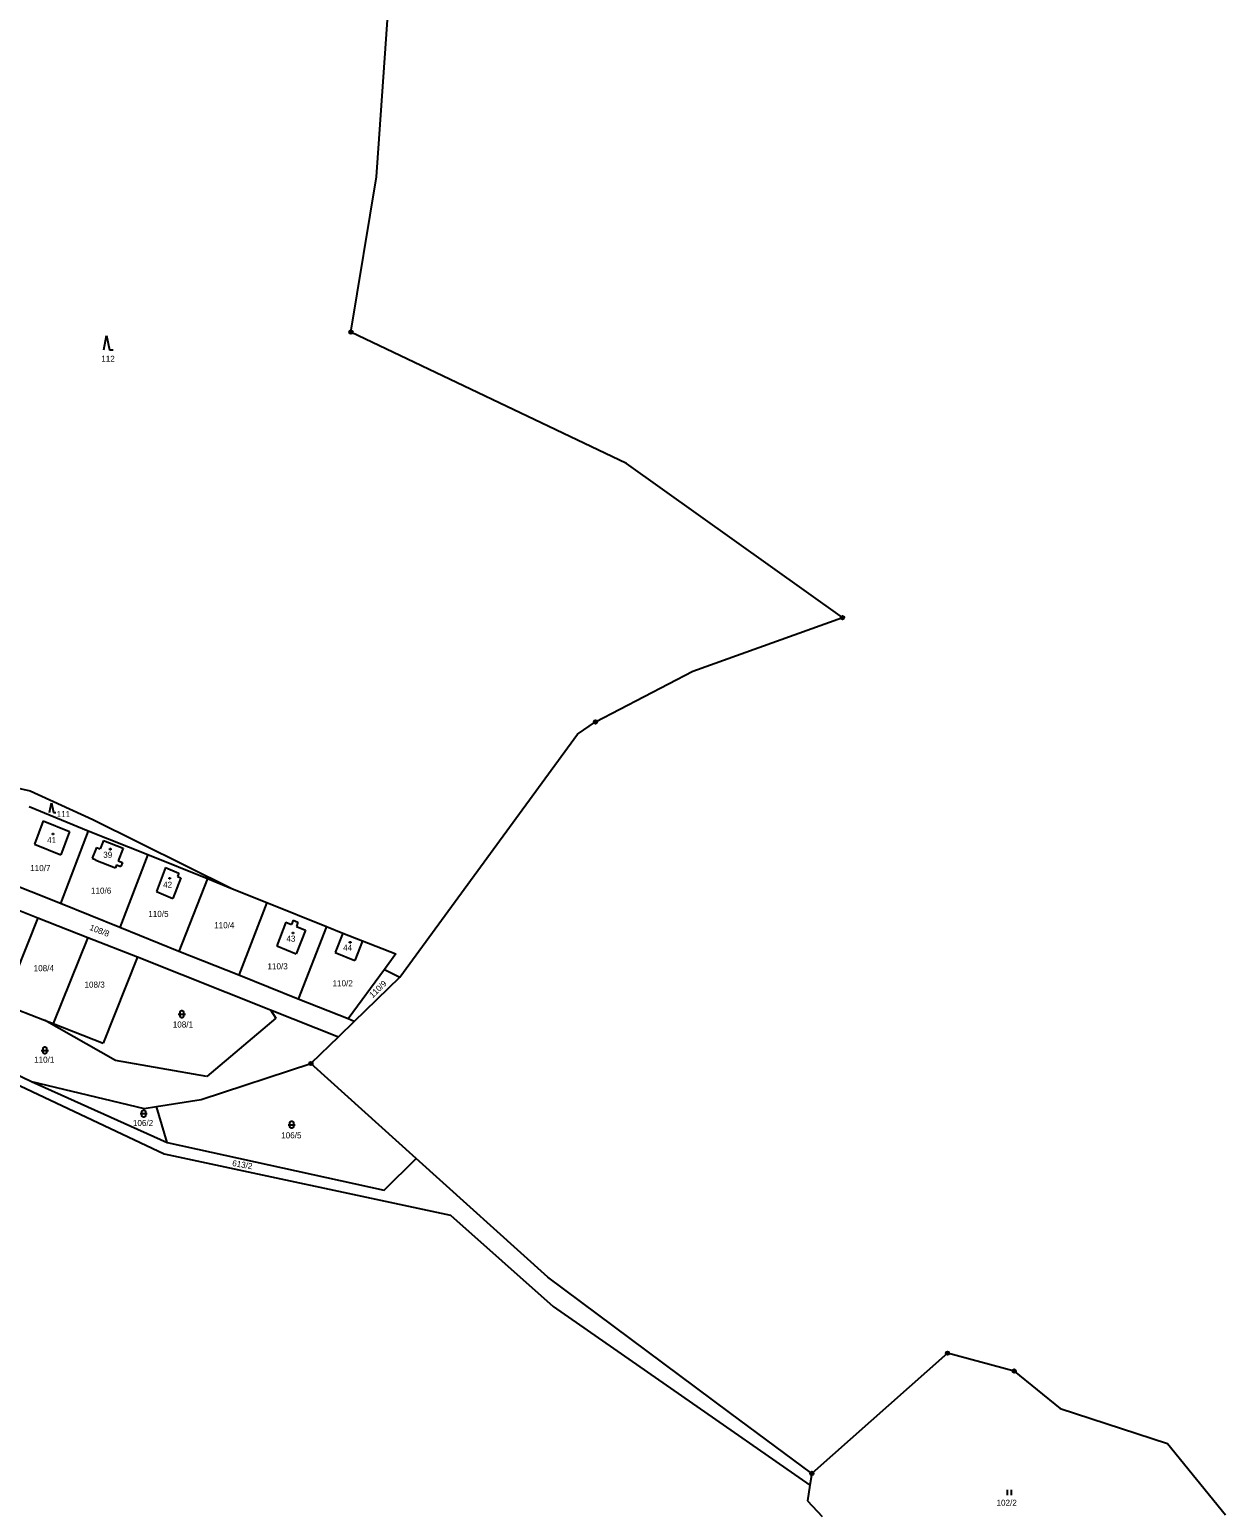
# Model space of a CAD drawing. Extents: x -794421 to -792735, y -1117671 to -1115559.
# Drawn here: x -793109.5 to -792774.2, y -1116832.2 to -1116417 of the extents above; entities that cross this region are included whole.
import ezdxf

# ---------------------------------------------------------------- set-up
doc = ezdxf.new("R2010")
doc.units = 0
for name, color, linetype in [('Vrstva 1', 7, 'Continuous'), ('Vrstva 14', 7, 'Continuous'), ('Vrstva 15', 7, 'Continuous'), ('Vrstva 23', 7, 'Continuous'), ('Vrstva 25', 7, 'Continuous'), ('Vrstva 28', 7, 'Continuous'), ('Vrstva 3', 7, 'Continuous'), ('Vrstva 4', 7, 'Continuous')]:
    doc.layers.add(name, color=color, linetype=linetype)

msp = doc.modelspace()

# ---------------------------------------------------------------- linework, layer by layer
at = {"layer": 'Vrstva 1'}
for p, q in [((-793154.11, -1116620.49), (-793109.33, -1116630.44)), ((-793109.33, -1116630.44), (-793091.78, -1116638.52)), ((-793109.67, -1116634.81), (-793093.04, -1116641.68)), ((-793105.7, -1116638.82), (-793108.16, -1116645.35)), ((-793105.7, -1116638.82), (-793098.28, -1116641.83)), ((-793091.78, -1116638.52), (-793052.59, -1116657.89)), ((-793093.04, -1116641.68), (-793100.84, -1116662.06)), ((-793098.28, -1116641.83), (-793100.74, -1116648.36)), ((-793093.04, -1116641.68), (-793076.37, -1116648.32)), ((-793088.79, -1116644.35), (-793089.72, -1116646.72)), ((-793088.79, -1116644.35), (-793083.29, -1116646.5)), ((-793108.16, -1116645.35), (-793100.74, -1116648.36)), ((-793090.74, -1116646.32), (-793091.92, -1116649.35)), ((-793090.74, -1116646.32), (-793089.72, -1116646.72)), ((-793083.29, -1116646.5), (-793084.66, -1116650.02)), ((-793076.37, -1116648.32), (-793084.21, -1116668.75)), ((-793076.37, -1116648.32), (-793059.64, -1116655.06)), ((-793091.92, -1116649.35), (-793090.9, -1116649.75)), ((-793090.9, -1116649.75), (-793090.95, -1116649.87)), ((-793090.95, -1116649.87), (-793085.44, -1116652.01)), ((-793085.11, -1116651.16), (-793085.44, -1116652.01)), ((-793085.11, -1116651.16), (-793083.92, -1116651.62)), ((-793084.66, -1116650.02), (-793083.47, -1116650.49)), ((-793083.47, -1116650.49), (-793083.92, -1116651.62)), ((-793071.36, -1116651.92), (-793073.93, -1116658.64)), ((-793071.36, -1116651.92), (-793067.63, -1116653.49)), ((-793100.84, -1116662.06), (-793117.32, -1116655.46)), ((-793067.13, -1116654.87), (-793069.32, -1116660.58)), ((-793067.63, -1116653.49), (-793068.02, -1116654.5)), ((-793068.02, -1116654.5), (-793067.13, -1116654.87)), ((-793059.64, -1116655.06), (-793067.62, -1116675.49)), ((-793059.64, -1116655.06), (-793052.59, -1116657.89)), ((-793121.12, -1116660.55), (-793107.16, -1116666.03)), ((-793073.93, -1116658.64), (-793069.32, -1116660.58)), ((-793052.59, -1116657.89), (-793042.94, -1116661.77)), ((-793084.21, -1116668.75), (-793100.84, -1116662.06)), ((-793042.94, -1116661.77), (-793050.85, -1116682.09)), ((-793042.94, -1116661.77), (-793026.25, -1116668.51)), ((-793107.16, -1116666.03), (-793116.82, -1116690.23)), ((-793107.16, -1116666.03), (-793093.19, -1116671.52)), ((-793067.62, -1116675.49), (-793084.21, -1116668.75)), ((-793037.65, -1116667.23), (-793040.16, -1116673.85)), ((-793037.65, -1116667.23), (-793036.03, -1116667.9)), ((-793035.58, -1116666.7), (-793036.03, -1116667.9)), ((-793035.58, -1116666.7), (-793034.24, -1116667.25)), ((-793032.15, -1116669.5), (-793034.72, -1116676.1)), ((-793034.24, -1116667.25), (-793034.7, -1116668.45)), ((-793034.7, -1116668.45), (-793032.15, -1116669.5)), ((-793026.25, -1116668.51), (-793034.18, -1116688.82)), ((-793026.25, -1116668.51), (-793021.71, -1116670.3)), ((-793093.19, -1116671.52), (-793102.85, -1116695.69)), ((-793093.19, -1116671.52), (-793079.23, -1116677)), ((-793021.71, -1116670.3), (-793023.77, -1116675.81)), ((-793021.71, -1116670.3), (-793016.19, -1116672.48)), ((-793016.19, -1116672.48), (-793018.26, -1116677.98)), ((-793016.19, -1116672.48), (-793006.82, -1116676.17)), ((-793079.23, -1116677), (-793088.88, -1116701.16)), ((-793079.23, -1116677), (-793041.96, -1116691.82)), ((-793050.85, -1116682.09), (-793067.62, -1116675.49)), ((-793040.16, -1116673.85), (-793034.72, -1116676.1)), ((-793023.77, -1116675.81), (-793018.26, -1116677.98)), ((-793006.82, -1116676.17), (-793010, -1116680.5)), ((-793010, -1116680.5), (-793020.21, -1116694.41)), ((-793010, -1116680.5), (-793005.71, -1116682.65)), ((-793175.39, -1116683.36), (-793071.81, -1116732.17)), ((-793034.18, -1116688.82), (-793050.85, -1116682.09)), ((-793161.81, -1116686.74), (-793108.95, -1116711.9)), ((-793116.82, -1116690.23), (-793105.32, -1116694.73)), ((-793020.21, -1116694.41), (-793034.18, -1116688.82)), ((-793040.49, -1116694.16), (-793059.84, -1116710.53)), ((-793041.96, -1116691.82), (-793040.49, -1116694.16)), ((-793041.96, -1116691.82), (-793022.91, -1116699.39)), ((-793018.5, -1116695.1), (-793020.21, -1116694.41)), ((-793105.32, -1116694.73), (-793102.85, -1116695.69)), ((-793085.37, -1116706.02), (-793105.32, -1116694.73)), ((-793102.85, -1116695.69), (-793088.88, -1116701.16)), ((-793059.84, -1116710.53), (-793085.37, -1116706.02)), ((-793061.38, -1116716.94), (-793030.61, -1116706.88)), ((-793108.95, -1116711.9), (-793077.4, -1116719.53)), ((-793108.95, -1116711.9), (-793070.89, -1116729.03)), ((-793077.4, -1116719.53), (-793073.91, -1116718.97)), ((-793073.91, -1116718.97), (-793061.38, -1116716.94)), ((-793070.89, -1116729.03), (-793073.91, -1116718.97)), ((-793070.89, -1116729.03), (-793010.09, -1116742.37)), ((-793071.81, -1116732.17), (-792991.43, -1116749.42)), ((-793010.09, -1116742.37), (-793001.09, -1116733.51)), ((-792991.43, -1116749.42), (-792962.66, -1116774.99)), ((-792962.66, -1116774.99), (-792890.67, -1116825.12)), ((-792890.14, -1116821.82), (-792890.67, -1116825.12)), ((-792890.67, -1116825.12), (-792891.38, -1116829.52)), ((-792891.38, -1116829.52), (-792887.25, -1116833.92))]:
    msp.add_line(p, q, dxfattribs=at)
at = {"layer": 'Vrstva 23'}
for p, q in [((-793088.7, -1116506.81), (-793087.9, -1116502.81)), ((-793087.9, -1116502.81), (-793087.1, -1116506.81)), ((-793087.1, -1116506.81), (-793086.1, -1116506.81)), ((-793103.896, -1116636.49), (-793103.36, -1116633.81)), ((-793103.36, -1116633.81), (-793102.824, -1116636.49)), ((-793102.824, -1116636.49), (-793102.154, -1116636.49)), ((-793067.82, -1116693.05), (-793065.82, -1116693.05)), ((-793067.32, -1116692.45), (-793067.22, -1116692.25)), ((-793067.32, -1116693.65), (-793067.32, -1116692.45)), ((-793067.22, -1116693.85), (-793067.32, -1116693.65)), ((-793067.22, -1116692.25), (-793067.12, -1116692.15)), ((-793067.12, -1116693.95), (-793067.22, -1116693.85)), ((-793067.12, -1116692.15), (-793066.92, -1116692.05)), ((-793066.92, -1116694.05), (-793067.12, -1116693.95)), ((-793066.92, -1116692.05), (-793066.72, -1116692.05)), ((-793066.72, -1116694.05), (-793066.92, -1116694.05)), ((-793066.72, -1116692.05), (-793066.52, -1116692.15)), ((-793066.52, -1116693.95), (-793066.72, -1116694.05)), ((-793066.52, -1116692.15), (-793066.42, -1116692.25)), ((-793066.42, -1116693.85), (-793066.52, -1116693.95)), ((-793066.42, -1116692.25), (-793066.32, -1116692.45)), ((-793066.32, -1116693.65), (-793066.42, -1116693.85)), ((-793066.32, -1116692.45), (-793066.32, -1116693.65)), ((-793105.73, -1116702.61), (-793105.63, -1116702.41)), ((-793105.73, -1116703.81), (-793105.73, -1116702.61)), ((-793105.63, -1116702.41), (-793105.53, -1116702.31)), ((-793105.53, -1116702.31), (-793105.33, -1116702.21)), ((-793105.33, -1116702.21), (-793105.13, -1116702.21)), ((-793105.13, -1116702.21), (-793104.93, -1116702.31)), ((-793104.93, -1116702.31), (-793104.83, -1116702.41)), ((-793104.83, -1116702.41), (-793104.73, -1116702.61)), ((-793104.73, -1116702.61), (-793104.73, -1116703.81)), ((-793106.23, -1116703.21), (-793104.23, -1116703.21)), ((-793105.63, -1116704.01), (-793105.73, -1116703.81)), ((-793105.53, -1116704.11), (-793105.63, -1116704.01)), ((-793105.33, -1116704.21), (-793105.53, -1116704.11)), ((-793105.13, -1116704.21), (-793105.33, -1116704.21)), ((-793104.93, -1116704.11), (-793105.13, -1116704.21)), ((-793104.83, -1116704.01), (-793104.93, -1116704.11)), ((-793104.73, -1116703.81), (-793104.83, -1116704.01)), ((-793078.5, -1116720.93), (-793076.5, -1116720.93)), ((-793078, -1116720.33), (-793077.9, -1116720.13)), ((-793078, -1116721.53), (-793078, -1116720.33)), ((-793077.9, -1116721.73), (-793078, -1116721.53)), ((-793077.9, -1116720.13), (-793077.8, -1116720.03)), ((-793077.8, -1116721.83), (-793077.9, -1116721.73)), ((-793077.8, -1116720.03), (-793077.6, -1116719.93)), ((-793077.6, -1116721.93), (-793077.8, -1116721.83)), ((-793077.6, -1116719.93), (-793077.4, -1116719.93)), ((-793077.4, -1116721.93), (-793077.6, -1116721.93)), ((-793077.4, -1116719.93), (-793077.2, -1116720.03)), ((-793077.2, -1116721.83), (-793077.4, -1116721.93)), ((-793077.2, -1116720.03), (-793077.1, -1116720.13)), ((-793077.1, -1116721.73), (-793077.2, -1116721.83)), ((-793077.1, -1116720.13), (-793077, -1116720.33)), ((-793077, -1116721.53), (-793077.1, -1116721.73)), ((-793077, -1116720.33), (-793077, -1116721.53)), ((-793036.52, -1116723.44), (-793036.42, -1116723.24)), ((-793036.52, -1116724.64), (-793036.52, -1116723.44)), ((-793036.42, -1116723.24), (-793036.32, -1116723.14)), ((-793036.32, -1116723.14), (-793036.12, -1116723.04)), ((-793036.12, -1116723.04), (-793035.92, -1116723.04)), ((-793035.92, -1116723.04), (-793035.72, -1116723.14)), ((-793035.72, -1116723.14), (-793035.62, -1116723.24)), ((-793035.62, -1116723.24), (-793035.52, -1116723.44)), ((-793035.52, -1116723.44), (-793035.52, -1116724.64)), ((-793037.02, -1116724.04), (-793035.02, -1116724.04)), ((-793036.42, -1116724.84), (-793036.52, -1116724.64)), ((-793036.32, -1116724.94), (-793036.42, -1116724.84)), ((-793036.12, -1116725.04), (-793036.32, -1116724.94)), ((-793035.92, -1116725.04), (-793036.12, -1116725.04)), ((-793035.72, -1116724.94), (-793035.92, -1116725.04)), ((-793035.62, -1116724.84), (-793035.72, -1116724.94)), ((-793035.52, -1116724.64), (-793035.62, -1116724.84)), ((-792835.29, -1116827.94), (-792835.29, -1116826.44)), ((-792834.29, -1116826.44), (-792834.29, -1116827.94))]:
    msp.add_line(p, q, dxfattribs=at)
at = {"layer": 'Vrstva 25'}
for p, q in [((-793103.06, -1116642.38), (-793102.76, -1116642.38)), ((-793103.06, -1116642.68), (-793103.06, -1116642.38)), ((-793102.76, -1116642.68), (-793103.06, -1116642.68)), ((-793102.76, -1116642.38), (-793102.76, -1116642.68)), ((-793087.05, -1116646.64), (-793086.75, -1116646.64)), ((-793087.05, -1116646.94), (-793087.05, -1116646.64)), ((-793086.75, -1116646.94), (-793087.05, -1116646.94)), ((-793086.75, -1116646.64), (-793086.75, -1116646.94)), ((-793070.37, -1116654.83), (-793070.07, -1116654.83)), ((-793070.37, -1116655.13), (-793070.37, -1116654.83)), ((-793070.07, -1116655.13), (-793070.37, -1116655.13)), ((-793070.07, -1116654.83), (-793070.07, -1116655.13)), ((-793035.78, -1116670.18), (-793035.48, -1116670.18)), ((-793035.78, -1116670.48), (-793035.78, -1116670.18)), ((-793035.48, -1116670.48), (-793035.78, -1116670.48)), ((-793035.48, -1116670.18), (-793035.48, -1116670.48)), ((-793019.76, -1116672.75), (-793019.46, -1116672.75)), ((-793019.76, -1116673.05), (-793019.76, -1116672.75)), ((-793019.46, -1116673.05), (-793019.76, -1116673.05)), ((-793019.46, -1116672.75), (-793019.46, -1116673.05))]:
    msp.add_line(p, q, dxfattribs=at)
at = {"layer": 'Vrstva 28'}
for centre, radius in [((-793019.38, -1116501.81), 0.5), ((-793019.38, -1116501.81), 0.01), ((-792881.54, -1116581.88), 0.5), ((-792881.54, -1116581.88), 0.01), ((-792950.8, -1116611.11), 0.5), ((-792950.8, -1116611.11), 0.01), ((-793030.61, -1116706.88), 0.5), ((-793030.61, -1116706.88), 0.01), ((-792852.1, -1116788.11), 0.5), ((-792852.1, -1116788.11), 0.01), ((-792833.43, -1116793.11), 0.5), ((-792833.43, -1116793.11), 0.01), ((-792890.14, -1116821.82), 0.5), ((-792890.14, -1116821.82), 0.01)]:
    msp.add_circle(centre, radius, dxfattribs=at)
at = {"layer": 'Vrstva 3'}
for p, q in [((-793012.18, -1116458.29), (-793006.64, -1116378.31)), ((-793019.38, -1116501.81), (-793012.18, -1116458.29)), ((-792942.1, -1116538.67), (-793019.38, -1116501.81)), ((-792881.54, -1116581.88), (-792942.1, -1116538.67)), ((-792923.52, -1116596.88), (-792881.54, -1116581.88)), ((-792950.8, -1116611.11), (-792923.52, -1116596.88)), ((-792955.86, -1116614.55), (-792950.8, -1116611.11)), ((-793005.71, -1116682.65), (-792955.86, -1116614.55)), ((-793018.5, -1116695.1), (-793005.71, -1116682.65)), ((-793018.5, -1116695.1), (-793022.91, -1116699.39)), ((-793022.91, -1116699.39), (-793030.61, -1116706.88)), ((-793001.09, -1116733.51), (-793030.61, -1116706.88)), ((-792964.22, -1116766.76), (-793001.09, -1116733.51)), ((-792913.27, -1116804.76), (-792964.22, -1116766.76)), ((-792852.1, -1116788.11), (-792890.14, -1116821.82)), ((-792833.43, -1116793.11), (-792852.1, -1116788.11)), ((-792890.14, -1116821.82), (-792913.27, -1116804.76))]:
    msp.add_line(p, q, dxfattribs=at)
at = {"layer": 'Vrstva 4'}
for p, q in [((-792833.43, -1116793.11), (-792820.51, -1116803.66)), ((-792820.51, -1116803.66), (-792790.45, -1116813.45)), ((-792790.45, -1116813.45), (-792774.18, -1116833.45))]:
    msp.add_line(p, q, dxfattribs=at)

# ---------------------------------------------------------------- texts
at = {"layer": 'Vrstva 14'}
for s, p in [('112', (-793089.413, -1116510.13)), ('111', (-793101.926, -1116637.82)), ('110/7', (-793109.342, -1116652.95)), ('110/6', (-793092.286, -1116659.27)), ('110/5', (-793076.222, -1116665.79)), ('110/4', (-793057.741, -1116668.96)), ('108/4', (-793108.368, -1116681.01)), ('110/3', (-793042.806, -1116680.49)), ('108/3', (-793094.112, -1116685.62)), ('110/2', (-793024.555, -1116685.25)), ('108/1', (-793069.355, -1116696.8)), ('110/1', (-793108.249, -1116706.66)), ('106/2', (-793080.532, -1116724.41)), ('106/5', (-793038.949, -1116727.87)), ('102/2', (-792838.352, -1116830.9))]:
    msp.add_text(s, height=1.7, dxfattribs=at).set_placement(p)
for s, rotation, p in [('108/8', 338.86287, (-793092.844, -1116669.384)), ('110/9', 43.82487, (-793013.293, -1116688.615)), ('613/2', 350.46675, (-793052.778, -1116735.619))]:
    msp.add_text(s, height=1.7, rotation=rotation, dxfattribs=at).set_placement(p)
at = {"layer": 'Vrstva 15'}
for s, p in [('41', (-793104.596, -1116645.11)), ('39', (-793088.857, -1116649.22)), ('42', (-793072.072, -1116657.61)), ('43', (-793037.493, -1116672.73)), ('44', (-793021.578, -1116675.26))]:
    msp.add_text(s, height=1.7, dxfattribs=at).set_placement(p)

doc.saveas('drawing.dxf')
